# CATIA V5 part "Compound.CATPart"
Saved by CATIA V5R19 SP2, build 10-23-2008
Part number: Compound
Definition: design
Nomenclature: Compound
Source: Unknown
Bounding box of the stored display mesh (mm): x 56 to 66.95, y -43.8 to -30.54, z -17.945 to 3.945
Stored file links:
  Z:\fausse table rondelle-20220905T211342Z-001\fausse table rondelle\Compound.CATPart
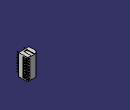
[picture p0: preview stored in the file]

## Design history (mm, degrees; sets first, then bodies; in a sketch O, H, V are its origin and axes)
AxisSystem1: origin (0, 0, 0), X (1, 0, 0), Y (0, 1, 0), Z (0, 0, 1)
Set1
  DatumSurface1 "CLOSED_SHELL #16540"
  DatumSurface2 "CLOSED_SHELL #17448"
  DatumSurface3 "CLOSED_SHELL #18356"
  DatumSurface4 "CLOSED_SHELL #18842"
  DatumSurface5 "CLOSED_SHELL #19750"
  DatumSurface6 "CLOSED_SHELL #20236"
  DatumSurface7 "CLOSED_SHELL #20722"
  DatumSurface8 "CLOSED_SHELL #21208"
  DatumSurface9 "CLOSED_SHELL #21694"
  DatumSurface10 "CLOSED_SHELL #25624"
  DatumSurface11 "CLOSED_SHELL #26110"
  DatumSurface12 "CLOSED_SHELL #26596"
  DatumSurface13 "CLOSED_SHELL #27082"
  DatumSurface14 "CLOSED_SHELL #27568"
  DatumSurface15 "CLOSED_SHELL #28054"
  DatumSurface16 "CLOSED_SHELL #28962"
  DatumSurface17 "CLOSED_SHELL #29448"
  DatumSurface18 "CLOSED_SHELL #29934"
  DatumSurface19 "CLOSED_SHELL #30420"
  DatumSurface20 "CLOSED_SHELL #31328"
  DatumSurface21 "CLOSED_SHELL #32236"
  DatumSurface22 "CLOSED_SHELL #32722"
  DatumSurface23 "CLOSED_SHELL #33630"
  DatumSurface24 "CLOSED_SHELL #34538"
  DatumSurface25 "CLOSED_SHELL #35024"
Body1 (main body)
